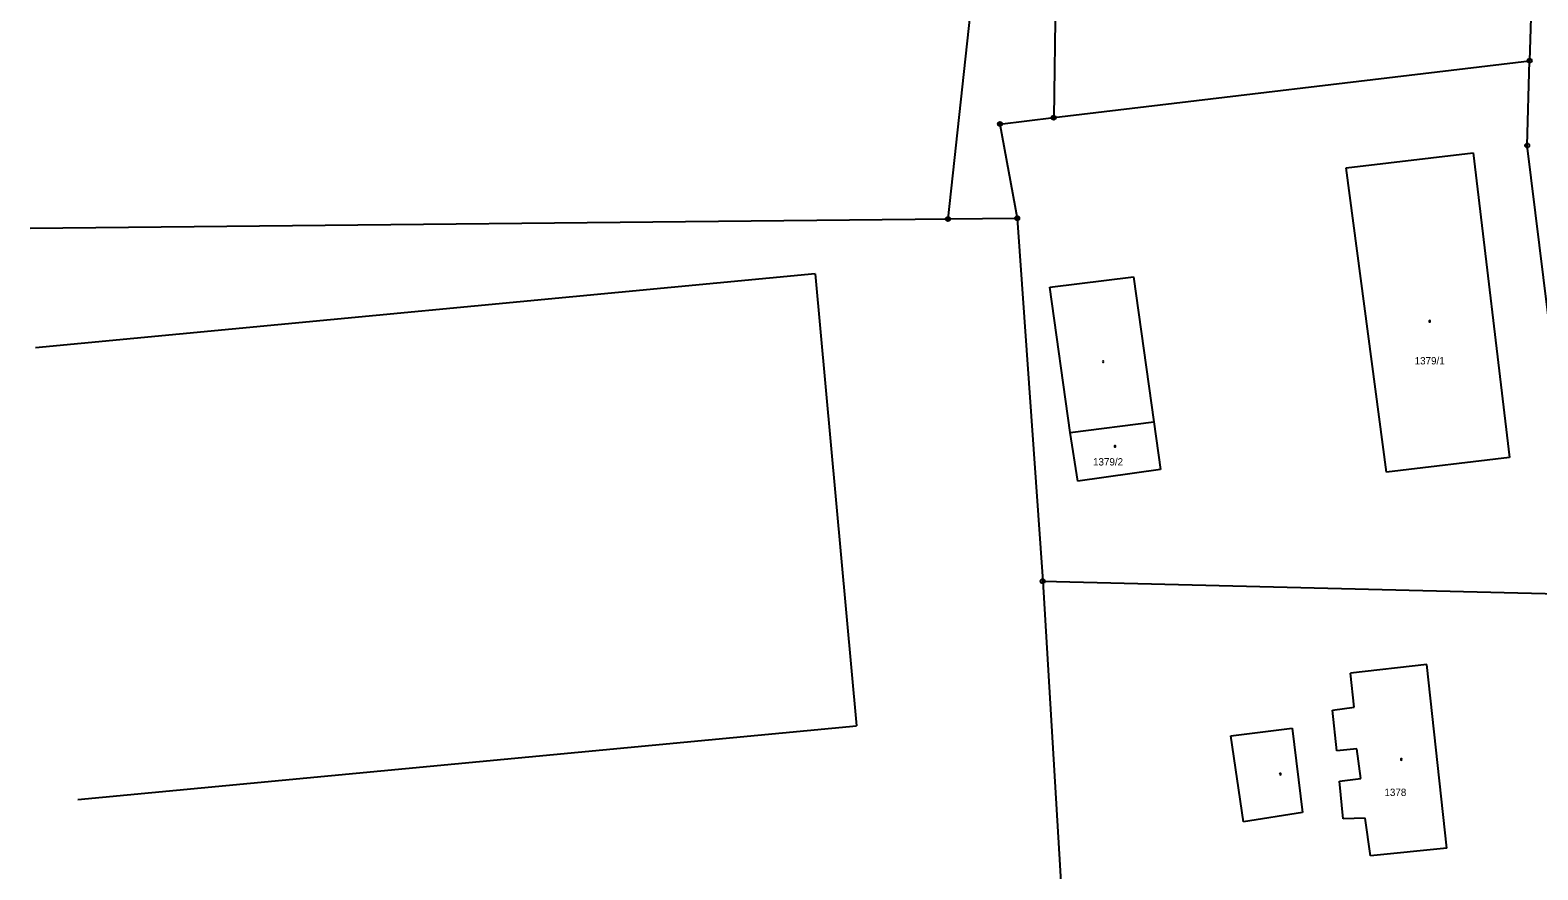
# Model space of a CAD drawing. Extents: x -454285 to -453563, y -1108687 to -1108249.
# Drawn here: x -454285.1 to -454141.3, y -1108543.6 to -1108463.6 of the extents above; entities that cross this region are included whole.
import ezdxf

# ---------------------------------------------------------------- set-up
doc = ezdxf.new("R2010")
doc.units = 0
for name, color, linetype in [('1', 7, 'Continuous'), ('15', 7, 'Continuous'), ('2', 7, 'Continuous'), ('25', 7, 'Continuous'), ('28', 7, 'Continuous')]:
    doc.layers.add(name, color=color, linetype=linetype)

# ---------------------------------------------------------------- blocks, each defined once
blk = doc.blocks.new('Z402')
for start, end in [(0, 180), (180, 0)]:
    blk.add_arc((0, 0), 0.15, start, end)
blk = doc.blocks.new('Z105')
for radius in [0.5, 0.01]:
    blk.add_circle((0, 0), radius)

msp = doc.modelspace()

# ---------------------------------------------------------------- linework, layer by layer
at = {"layer": '1'}
for p, q in [((-454187.14, -1108450.29), (-454187.48, -1108471.9)), ((-454141.77, -1108454.42), (-454142.11, -1108466.47)), ((-454187.48, -1108471.9), (-454142.11, -1108466.47)), ((-454142.34, -1108474.56), (-454142.11, -1108466.47)), ((-454192.6, -1108472.51), (-454187.48, -1108471.9)), ((-454192.6, -1108472.51), (-454190.96, -1108481.5)), ((-454137.07, -1108517.39), (-454142.34, -1108474.56)), ((-454285.06, -1108482.46), (-454197.57, -1108481.57)), ((-454197.57, -1108481.57), (-454190.96, -1108481.5)), ((-454190.96, -1108481.5), (-454188.53, -1108516.12)), ((-454210.21, -1108486.79), (-454284.56, -1108493.86)), ((-454210.21, -1108486.79), (-454206.29, -1108529.92)), ((-454185.9, -1108501.94), (-454177.94, -1108500.91)), ((-454177.94, -1108500.91), (-454177.31, -1108505.47)), ((-454185.18, -1108506.56), (-454185.9, -1108501.94)), ((-454177.31, -1108505.47), (-454185.18, -1108506.56)), ((-454188.53, -1108516.12), (-454186.51, -1108549.78)), ((-454188.53, -1108516.12), (-454137.07, -1108517.39)), ((-454280.52, -1108536.92), (-454206.29, -1108529.92))]:
    msp.add_line(p, q, dxfattribs=at)
msp.add_lwpolyline([(-454175.74, -1108417.43), (-454190.43, -1108415.64), (-454197.57, -1108481.57)], dxfattribs=at)
at = {"layer": '2'}
for p, q in [((-454159.59, -1108476.7), (-454147.49, -1108475.27)), ((-454147.49, -1108475.27), (-454144.03, -1108504.32)), ((-454155.77, -1108505.71), (-454159.59, -1108476.7)), ((-454187.86, -1108488.07), (-454179.86, -1108487.08)), ((-454179.86, -1108487.08), (-454177.94, -1108500.91)), ((-454185.9, -1108501.94), (-454187.86, -1108488.07)), ((-454144.03, -1108504.32), (-454155.77, -1108505.71)), ((-454151.9, -1108524.05), (-454159.2, -1108524.9)), ((-454150, -1108541.57), (-454151.9, -1108524.05)), ((-454158.85, -1108528.13), (-454159.2, -1108524.9)), ((-454160.89, -1108528.43), (-454158.85, -1108528.13)), ((-454160.5, -1108532.3), (-454160.89, -1108528.43)), ((-454170.59, -1108530.87), (-454164.76, -1108530.14)), ((-454164.76, -1108530.14), (-454163.76, -1108538.17)), ((-454169.4, -1108539.06), (-454170.59, -1108530.87)), ((-454158.58, -1108532.09), (-454160.5, -1108532.3)), ((-454158.19, -1108534.92), (-454158.58, -1108532.09)), ((-454160.23, -1108535.18), (-454158.19, -1108534.92)), ((-454159.88, -1108538.78), (-454160.23, -1108535.18)), ((-454163.76, -1108538.17), (-454169.4, -1108539.06)), ((-454157.8, -1108538.72), (-454159.88, -1108538.78)), ((-454157.29, -1108542.31), (-454157.8, -1108538.72)), ((-454150, -1108541.57), (-454157.29, -1108542.31))]:
    msp.add_line(p, q, dxfattribs=at)

# ---------------------------------------------------------------- block references
at = {"layer": '25', "xscale": 0.4, "yscale": 0.4000000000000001}
for p in [(-454151.64, -1108491.32), (-454182.76, -1108495.17), (-454181.64, -1108503.25), (-454154.33, -1108533.11), (-454165.88, -1108534.51)]:
    msp.add_blockref('Z402', p, dxfattribs=at)
at = {"layer": '28', "xscale": 0.4, "yscale": 0.4000000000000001}
for p in [(-454142.11, -1108466.47), (-454192.6, -1108472.51), (-454187.48, -1108471.9), (-454142.34, -1108474.56), (-454197.57, -1108481.57), (-454190.96, -1108481.5), (-454188.53, -1108516.12)]:
    msp.add_blockref('Z105', p, dxfattribs=at)

# ---------------------------------------------------------------- texts
at = {"layer": '15'}
for s, p in [('1379/1', (-454153.07, -1108495.44)), ('1379/2', (-454183.73, -1108505.08)), ('1378', (-454155.95, -1108536.6))]:
    msp.add_text(s, height=0.7, dxfattribs=at).set_placement(p)

doc.saveas('drawing.dxf')
